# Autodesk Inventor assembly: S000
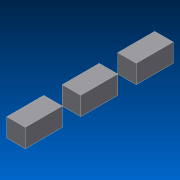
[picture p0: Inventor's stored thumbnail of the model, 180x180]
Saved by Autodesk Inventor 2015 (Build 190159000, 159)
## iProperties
Created: 2017-11
Part Number: S000
Document SubType Name: Assembly
Designer: navara
Mass: 6 g
Surface Area: 30 cm^2
Volume: 6 cm^3
Density: 1 g/cm^3
Author: navara
Last Saved By: navara
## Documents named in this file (4)
- D:\Dokumenty\CAD_DATA\Inventor_2015\Projekty\SOUCASTKY_2015\20171120\S000.iam
- D:\Dokumenty\CAD_DATA\Inventor_2015\Projekty\SOUCASTKY_2015\20171120\P100.ipt
- D:\Dokumenty\CAD_DATA\Inventor_2015\Projekty\SOUCASTKY_2015\20171120\Q300.ipt
- D:\Dokumenty\CAD_DATA\Inventor_2015\Projekty\SOUCASTKY_2015\20171120\S200.ipt
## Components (3 placed, 3 different names)
1. P100:1
2. S200:1
3. Q300:1
